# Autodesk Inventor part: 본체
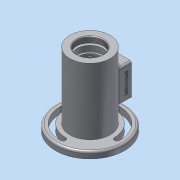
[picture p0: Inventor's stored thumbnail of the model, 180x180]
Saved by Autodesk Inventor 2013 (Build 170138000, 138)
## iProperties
Created: 2017-05
Part Number: 본체
Material: 알루미늄 6061
Document SubType Name: Modeling
Designer: Administrator
Density: 2.71 g/cm^3
Mass: 681.255 g
Surface Area: 619.851 cm^2
Volume: 251.386 cm^3
Author: Administrator
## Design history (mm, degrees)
sketch "스케치1"
  geometry: C1 r 31 at (0, 0); 1 further point
  constraints: 1 centre point, 1 coincident
  dimensions: "d0" = 62 diameter of C1
extrude "돌출1" new body sketch "스케치1" distance "d2" = 56; taper "d4" = 0 deg; dims "d3" = 59, "d5" = 0
hole "구멍1" diameter "d13" = 35; stored, may be unused: countersink angle "d17" = 90 deg, drill point angle "d19" = 0 deg; dims "d11" = 10, "d12" = 10, "d14" = 6, "d15" = 52, "d16" = 19, "d18" = 30
sketch "스케치3"
  geometry: C1 r 31 at (0, 0) reference; C2 r 53 at (0, 0)
  constraints: 1 centre point, 1 coincident
  dimensions: "d20" = 106 diameter of C2
extrude "돌출3" join sketch "스케치3" distance "d22" = 10; taper "d23" = 0 deg
sketch "스케치4"
  geometry: C1 r 31 at (0, 0) reference
extrude "돌출4" join sketch "스케치4" distance "d24" = 3; taper "d25" = 0 deg
node "작업 평면2"
sketch "스케치5"
  geometry: L1 (-20, -25)-(20, -25); L2 (20, -25)-(20, 25); L3 (20, 25)-(-20, 25); L4 (-20, 25)-(-20, -25); L5 (-20, -25)-(20, 25); L6 (20, -25)-(-20, 25); 1 further point
  constraints: 12 end point, 2 midpoint, 2 parallel, 1 horizontal, 1 perpendicular
  dimensions: "d27" = 40 distance of L2.end L3.end; "d29" = 50 distance of L1.end L2.end
extrude "돌출5" join sketch "스케치5" stored distance "d30" = 3; taper "d31" = 0 deg
hole "구멍2" diameter "d34" = 40.376; stored, may be unused: countersink angle "d38" = 90 deg, drill point angle "d40" = 0 deg; dims "d32" = 10, "d33" = 10, "d35" = 6, "d36" = 52, "d37" = 19, "d39" = 9
hole "구멍3" diameter "d43" = 40; stored, may be unused: countersink angle "d47" = 90 deg, drill point angle "d49" = 0 deg; dims "d41" = 10, "d42" = 10, "d44" = 6, "d45" = 48, "d46" = 3, "d48" = 12
hole "구멍4" diameter "d52" = 35; stored, may be unused: countersink angle "d56" = 90 deg, drill point angle "d58" = 0 deg; dims "d50" = 10, "d51" = 10, "d53" = 6, "d54" = 35, "d55" = 3, "d57" = 3.25
hole "구멍5" diameter "d61" = 37; stored, may be unused: countersink angle "d65" = 90 deg, drill point angle "d67" = 0 deg; dims "d59" = 10, "d60" = 10, "d62" = 6, "d63" = 35, "d64" = 3, "d66" = 1.75
sketch "스케치6"
  geometry: L1 (0, -59)-(22, -59); L2 (22, -59)-(16, -45); L3 (16, -45)-(0, -45); L4 (0, -45)-(0, -59); L5 (-31, -59)-(31, -59) reference; 4 further points
  constraints: 8 end point, 3 midpoint, 1 horizontal alignment, 1 parallel, 1 perpendicular, 1 vertical, 1 vertical alignment
  dimensions: "d68" = 22 distance of L1.start L1.end; "d70" = 16 distance of L2.end L3.end; "d71" = 14 distance between parallel lines of L1 L3
revolve "회전1" sketch "스케치6" stored, may be unused: angle "d72" = 90 deg
hole "구멍6" diameter "d75" = 20; stored, may be unused: countersink angle "d79" = 90 deg, drill point angle "d81" = 0 deg; dims "d73" = 10, "d74" = 10, "d76" = 6, "d77" = 25, "d78" = 7.3, "d80" = 10
hole "구멍7" diameter "d84" = 33; stored, may be unused: countersink angle "d88" = 90 deg, drill point angle "d90" = 0 deg; dims "d82" = 10, "d83" = 10, "d85" = 6, "d86" = 25, "d87" = 7.3, "d89" = 5
sketch "스케치7"
  geometry: L1 (-11, -16)-(11, -16); L2 (11, -16)-(11, 16); L3 (11, 16)-(-11, 16); L4 (-11, 16)-(-11, -16); L5 (-11, -16)-(11, 16); L6 (11, -16)-(-11, 16); 1 further point
  constraints: 12 end point, 2 midpoint, 2 parallel, 1 horizontal, 1 perpendicular
  dimensions: "d91" = 22 distance of L2.end L3.end; "d93" = 32 distance of L3.end L1.start
extrude "돌출6" cut sketch "스케치7" stored distance "d94" = 3; taper "d95" = 0 deg
hole "구멍8" diameter "d98" = 2.459; stored, may be unused: countersink angle "d102" = 90 deg, drill point angle "d104" = 118 deg; dims "d96" = 4.5, "d97" = 4.5, "d99" = 6, "d100" = 25, "d101" = 7.3, "d103" = 8
sketch "스케치8"
  geometry: C1 r 31 at (0, 0) reference; C2 r 53 at (0, 0) reference; A1 r 41.5 centre (0, 0) between (-41.5, 0) and (0, 41.5); A2 r 4 centre (-41.5, 0) between (-45.5, 0) and (-37.5, 0); A3 r 4 centre (0, 41.5) between (0, 37.5) and (0, 45.5); A4 r 4 centre (41.5, 0) between (45.5, 0) and (37.5, 0); A5 r 4 centre (0, -41.5) between (0, -37.5) and (0, -45.5); A6 r 37.5 centre (0, 0) between (0, 37.5) and (-37.5, 0); A7 r 37.5 centre (0, 0) between (0, -37.5) and (37.5, 0); A8 r 45.5 centre (0, 0) between (0, 45.5) and (-45.5, 0); A9 r 45.5 centre (0, 0) between (0, -45.5) and (45.5, 0)
  constraints: 20 point on circle, 9 centre point, 3 coincident, 3 equal radius, 2 horizontal alignment, 2 vertical alignment
  dimensions: "d111" = 83 diameter of A1; "d115" = 8 diameter of A4; "d116" = 37.5 radius of A6; "d117" = 45.5 radius of A8; "d118" = 45.5 radius of A9; "d119" = 37.5 radius of A7
extrude "돌출7" cut sketch "스케치8" stored distance "d120" = 3; taper "d121" = 0 deg
chamfer "모따기4" distance "d139" = 0.7; stored, may be unused: second distance "d140" = 2, angle "d141" = 30 deg
fillet "모깎기2" dims "d126" = 0.3
fillet "모깎기3" dims "d127" = 3
chamfer "모따기2" distance "d128" = 1; stored, may be unused: second distance "d129" = 2, angle "d130" = 50 deg
fillet "모깎기4" dims "d131" = 3
chamfer "모따기3" distance "d132" = 1; stored, may be unused: second distance "d133" = 2, angle "d134" = 50 deg
sketch "스케치9"
  geometry: L1 (0, 0)-(44, 0) reference; L2 (-34, -13)-(-34, -75) reference; 2 further points
  constraints: 1 other
  dimensions: "d135" = 8 distance from line of point (22, -8) L1; "d136" = 56 distance from line of L2 point (22, -8)
feature "엠보싱1" sketch "스케치9" dims "d137" = 0.5, "d138" = 0
node "솔리드1"
mirror "대칭1"
pattern_linear "직사각형 패턴1" dims "d107" = 31, "d110" = 41
other parameters: "d26" = 44, "d113" = 91, "d114" = 75
